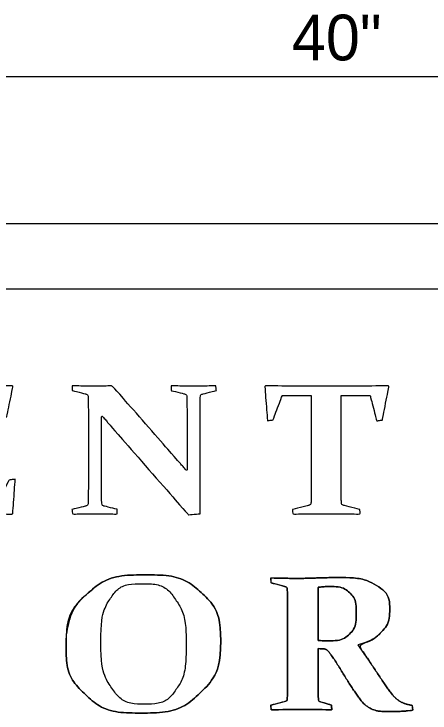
# Model space of a CAD drawing. Extents: x 60714 to 61343, y 7599 to 7998.
# Drawn here: x 60981.17 to 61006.63, y 7950.27 to 7993.09 of the extents above; entities that cross this region are included whole.
import ezdxf

# ---------------------------------------------------------------- set-up
doc = ezdxf.new("R2010")
doc.units = 0
for name, color, linetype in [('2', 7, 'Continuous'), ('Default', 7, 'Continuous'), ('SignPanel', 7, 'Continuous')]:
    doc.layers.add(name, color=color, linetype=linetype)

# ---------------------------------------------------------------- blocks, each defined once
blk = doc.blocks.new('block 5')
at = {"layer": 'Default'}
for points in [[(437.3, -454.8), (437.3, -454.8), (448.38, -454.8), (448.38, -454.8), (455.48, -454.8), (462.84, -454.75), (470.47, -454.63), (470.47, -454.63), (470.77, -454.98), (470.77, -454.98), (470.77, -454.98), (468.06, -469.57), (468.06, -469.57), (468.06, -469.57), (465.69, -469.92), (465.69, -469.92), (465.69, -469.92), (462.89, -459.27), (462.89, -459.27), (462.89, -459.27), (445.93, -459.27), (445.93, -459.27), (445.93, -459.27), (445.93, -482.54), (445.93, -482.54), (445.93, -482.54), (448.3, -482.54), (448.3, -482.54), (450.84, -482.54), (453.57, -482.51), (456.49, -482.45), (457.25, -482.42), (457.75, -482.03), (457.98, -481.27), (457.98, -481.27), (459.56, -475.27), (459.56, -475.27), (459.56, -475.27), (462.45, -475.13), (462.45, -475.13), (462.36, -479.37), (462.32, -482.54), (462.32, -484.64), (462.32, -486.69), (462.36, -489.81), (462.45, -494.02), (462.45, -494.02), (459.56, -494.24), (459.56, -494.24), (459.56, -494.24), (457.94, -488.06), (457.94, -488.06), (457.7, -487.27), (457.25, -486.86), (456.58, -486.83), (453.6, -486.78), (450.82, -486.75), (448.25, -486.75), (448.25, -486.75), (445.93, -486.75), (445.93, -486.75), (445.93, -486.75), (445.93, -501.78), (445.93, -501.78), (445.93, -504.99), (445.96, -508.17), (446.02, -511.33), (446.02, -511.33), (463.54, -511.33), (463.54, -511.33), (463.54, -511.33), (469.06, -499.8), (469.06, -499.8), (469.06, -499.8), (471.74, -499.41), (471.74, -499.41), (471.74, -499.41), (470.69, -515.8), (470.69, -515.8), (470.69, -515.8), (470.38, -516.1), (470.38, -516.1), (463.11, -516.02), (456.02, -515.97), (449.13, -515.97), (449.13, -515.97), (437.52, -515.97), (437.52, -515.97), (433.75, -515.97), (429.86, -516.02), (425.86, -516.1), (425.86, -516.1), (425.64, -513.91), (425.64, -513.91), (425.64, -513.91), (431.51, -512.29), (431.51, -512.29), (432.24, -512.09), (432.64, -511.64), (432.7, -510.93), (432.73, -509.77), (432.75, -508.46), (432.76, -507.01), (432.78, -505.57), (432.78, -503.97), (432.78, -502.21), (432.78, -502.21), (432.78, -467.29), (432.78, -467.29), (432.78, -465.83), (432.78, -464.5), (432.76, -463.3), (432.75, -462.11), (432.73, -461.01), (432.7, -460.02), (432.67, -459.26), (432.32, -458.78), (431.64, -458.57), (431.64, -458.57), (425.77, -456.86), (425.77, -456.86), (425.77, -456.86), (425.64, -454.63), (425.64, -454.63), (429.73, -454.75), (433.62, -454.8), (437.3, -454.8)], [(437.3, -454.8), (437.3, -454.8), (448.38, -454.8), (448.38, -454.8), (455.48, -454.8), (462.84, -454.75), (470.47, -454.63), (470.47, -454.63), (470.77, -454.98), (470.77, -454.98), (470.77, -454.98), (468.06, -469.57), (468.06, -469.57), (468.06, -469.57), (465.69, -469.92), (465.69, -469.92), (465.69, -469.92), (462.89, -459.27), (462.89, -459.27), (462.89, -459.27), (445.93, -459.27), (445.93, -459.27), (445.93, -459.27), (445.93, -482.54), (445.93, -482.54), (445.93, -482.54), (448.3, -482.54), (448.3, -482.54), (450.84, -482.54), (453.57, -482.51), (456.49, -482.45), (457.25, -482.42), (457.75, -482.03), (457.98, -481.27), (457.98, -481.27), (459.56, -475.27), (459.56, -475.27), (459.56, -475.27), (462.45, -475.13), (462.45, -475.13), (462.36, -479.37), (462.32, -482.54), (462.32, -484.64), (462.32, -486.69), (462.36, -489.81), (462.45, -494.02), (462.45, -494.02), (459.56, -494.24), (459.56, -494.24), (459.56, -494.24), (457.94, -488.06), (457.94, -488.06), (457.7, -487.27), (457.25, -486.86), (456.58, -486.83), (453.6, -486.78), (450.82, -486.75), (448.25, -486.75), (448.25, -486.75), (445.93, -486.75), (445.93, -486.75), (445.93, -486.75), (445.93, -501.78), (445.93, -501.78), (445.93, -504.99), (445.96, -508.17), (446.02, -511.33), (446.02, -511.33), (463.54, -511.33), (463.54, -511.33), (463.54, -511.33), (469.06, -499.8), (469.06, -499.8), (469.06, -499.8), (471.74, -499.41), (471.74, -499.41), (471.74, -499.41), (470.69, -515.8), (470.69, -515.8), (470.69, -515.8), (470.38, -516.1), (470.38, -516.1), (463.11, -516.02), (456.02, -515.97), (449.13, -515.97), (449.13, -515.97), (437.52, -515.97), (437.52, -515.97), (433.75, -515.97), (429.86, -516.02), (425.86, -516.1), (425.86, -516.1), (425.64, -513.91), (425.64, -513.91), (425.64, -513.91), (431.51, -512.29), (431.51, -512.29), (432.24, -512.09), (432.64, -511.64), (432.7, -510.93), (432.73, -509.77), (432.75, -508.46), (432.76, -507.01), (432.78, -505.57), (432.78, -503.97), (432.78, -502.21), (432.78, -502.21), (432.78, -467.29), (432.78, -467.29), (432.78, -465.83), (432.78, -464.5), (432.76, -463.3), (432.75, -462.11), (432.73, -461.01), (432.7, -460.02), (432.67, -459.26), (432.32, -458.78), (431.64, -458.57), (431.64, -458.57), (425.77, -456.86), (425.77, -456.86), (425.77, -456.86), (425.64, -454.63), (425.64, -454.63), (429.73, -454.75), (433.62, -454.8), (437.3, -454.8)], [(509.49, -510.76), (509.52, -511.61), (509.89, -512.12), (510.59, -512.29), (510.59, -512.29), (516.2, -513.83), (516.2, -513.83), (516.2, -513.83), (516.33, -516.1), (516.33, -516.1), (512.38, -516.02), (509.14, -515.97), (506.6, -515.97), (504.09, -515.97), (500.8, -516.02), (496.74, -516.1), (496.74, -516.1), (496.52, -513.91), (496.52, -513.91), (496.52, -513.91), (502.39, -512.29), (502.39, -512.29), (503.15, -512.06), (503.55, -511.61), (503.58, -510.93), (503.63, -508.57), (503.66, -505.66), (503.66, -502.21), (503.66, -502.21), (503.66, -467.29), (503.66, -467.29), (503.66, -464.37), (503.63, -461.95), (503.58, -460.02), (503.55, -459.26), (503.2, -458.78), (502.52, -458.57), (502.52, -458.57), (496.65, -456.86), (496.65, -456.86), (496.65, -456.86), (496.52, -454.63), (496.52, -454.63), (500.61, -454.75), (503.75, -454.8), (505.94, -454.8), (508.8, -454.8), (511.52, -454.75), (514.09, -454.63), (514.09, -454.63), (543.23, -491.13), (543.23, -491.13), (544.4, -492.59), (545.6, -494.14), (546.82, -495.77), (546.77, -493.76), (546.74, -491.81), (546.74, -489.95), (546.74, -489.95), (546.74, -467.12), (546.74, -467.12), (546.74, -464.28), (546.71, -461.84), (546.65, -459.8), (546.62, -459.13), (546.24, -458.69), (545.51, -458.48), (545.51, -458.48), (539.9, -456.95), (539.9, -456.95), (539.9, -456.95), (539.77, -454.63), (539.77, -454.63), (543.8, -454.75), (547.07, -454.8), (549.58, -454.8), (552.16, -454.8), (555.41, -454.75), (559.36, -454.63), (559.36, -454.63), (559.57, -456.86), (559.57, -456.86), (559.57, -456.86), (553.62, -458.57), (553.62, -458.57), (552.94, -458.78), (552.59, -459.26), (552.56, -460.02), (552.48, -461.95), (552.43, -464.37), (552.43, -467.29), (552.43, -467.29), (552.43, -515.97), (552.43, -515.97), (552.43, -515.97), (547.39, -516.45), (547.39, -516.45), (547.39, -516.45), (512.87, -473.21), (512.87, -473.21), (511.84, -471.89), (510.66, -470.33), (509.32, -468.52), (509.37, -470.68), (509.4, -472.67), (509.4, -474.48), (509.4, -474.48), (509.4, -502.21), (509.4, -502.21), (509.4, -505.66), (509.43, -508.51), (509.49, -510.76)], [(509.49, -510.76), (509.52, -511.61), (509.89, -512.12), (510.59, -512.29), (510.59, -512.29), (516.2, -513.83), (516.2, -513.83), (516.2, -513.83), (516.33, -516.1), (516.33, -516.1), (512.38, -516.02), (509.14, -515.97), (506.6, -515.97), (504.09, -515.97), (500.8, -516.02), (496.74, -516.1), (496.74, -516.1), (496.52, -513.91), (496.52, -513.91), (496.52, -513.91), (502.39, -512.29), (502.39, -512.29), (503.15, -512.06), (503.55, -511.61), (503.58, -510.93), (503.63, -508.57), (503.66, -505.66), (503.66, -502.21), (503.66, -502.21), (503.66, -467.29), (503.66, -467.29), (503.66, -464.37), (503.63, -461.95), (503.58, -460.02), (503.55, -459.26), (503.2, -458.78), (502.52, -458.57), (502.52, -458.57), (496.65, -456.86), (496.65, -456.86), (496.65, -456.86), (496.52, -454.63), (496.52, -454.63), (500.61, -454.75), (503.75, -454.8), (505.94, -454.8), (508.8, -454.8), (511.52, -454.75), (514.09, -454.63), (514.09, -454.63), (543.23, -491.13), (543.23, -491.13), (544.4, -492.59), (545.6, -494.14), (546.82, -495.77), (546.77, -493.76), (546.74, -491.81), (546.74, -489.95), (546.74, -489.95), (546.74, -467.12), (546.74, -467.12), (546.74, -464.28), (546.71, -461.84), (546.65, -459.8), (546.62, -459.13), (546.24, -458.69), (545.51, -458.48), (545.51, -458.48), (539.9, -456.95), (539.9, -456.95), (539.9, -456.95), (539.77, -454.63), (539.77, -454.63), (543.8, -454.75), (547.07, -454.8), (549.58, -454.8), (552.16, -454.8), (555.41, -454.75), (559.36, -454.63), (559.36, -454.63), (559.57, -456.86), (559.57, -456.86), (559.57, -456.86), (553.62, -458.57), (553.62, -458.57), (552.94, -458.78), (552.59, -459.26), (552.56, -460.02), (552.48, -461.95), (552.43, -464.37), (552.43, -467.29), (552.43, -467.29), (552.43, -515.97), (552.43, -515.97), (552.43, -515.97), (547.39, -516.45), (547.39, -516.45), (547.39, -516.45), (512.87, -473.21), (512.87, -473.21), (511.84, -471.89), (510.66, -470.33), (509.32, -468.52), (509.37, -470.68), (509.4, -472.67), (509.4, -474.48), (509.4, -474.48), (509.4, -502.21), (509.4, -502.21), (509.4, -505.66), (509.43, -508.51), (509.49, -510.76)], [(607.67, -515.97), (602.53, -515.97), (597.62, -516.02), (592.94, -516.1), (592.94, -516.1), (592.73, -513.91), (592.73, -513.91), (592.73, -513.91), (599.74, -511.99), (599.74, -511.99), (600.47, -511.75), (600.85, -511.28), (600.88, -510.58), (600.93, -508.39), (600.96, -505.57), (600.96, -502.13), (600.96, -502.13), (600.96, -459.32), (600.96, -459.32), (600.96, -459.32), (588.34, -459.32), (588.34, -459.32), (588.34, -459.32), (584.31, -470.97), (584.31, -470.97), (584.31, -470.97), (581.86, -471.37), (581.86, -471.37), (581.86, -471.37), (580.72, -454.98), (580.72, -454.98), (580.72, -454.98), (581.03, -454.63), (581.03, -454.63), (588.21, -454.75), (595.09, -454.8), (601.66, -454.8), (601.66, -454.8), (613.89, -454.8), (613.89, -454.8), (620.46, -454.8), (627.39, -454.75), (634.66, -454.63), (634.66, -454.63), (634.92, -454.98), (634.92, -454.98), (634.92, -454.98), (632.03, -471.02), (632.03, -471.02), (632.03, -471.02), (629.58, -471.41), (629.58, -471.41), (629.58, -471.41), (626.73, -459.32), (626.73, -459.32), (626.73, -459.32), (614.06, -459.32), (614.06, -459.32), (614.06, -459.32), (614.06, -502.13), (614.06, -502.13), (614.06, -505.57), (614.09, -508.39), (614.15, -510.58), (614.18, -511.28), (614.58, -511.75), (615.34, -511.99), (615.34, -511.99), (622.21, -513.91), (622.21, -513.91), (622.21, -513.91), (622.35, -516.1), (622.35, -516.1), (617.5, -516.02), (612.6, -515.97), (607.67, -515.97)], [(607.67, -515.97), (602.53, -515.97), (597.62, -516.02), (592.94, -516.1), (592.94, -516.1), (592.73, -513.91), (592.73, -513.91), (592.73, -513.91), (599.74, -511.99), (599.74, -511.99), (600.47, -511.75), (600.85, -511.28), (600.88, -510.58), (600.93, -508.39), (600.96, -505.57), (600.96, -502.13), (600.96, -502.13), (600.96, -459.32), (600.96, -459.32), (600.96, -459.32), (588.34, -459.32), (588.34, -459.32), (588.34, -459.32), (584.31, -470.97), (584.31, -470.97), (584.31, -470.97), (581.86, -471.37), (581.86, -471.37), (581.86, -471.37), (580.72, -454.98), (580.72, -454.98), (580.72, -454.98), (581.03, -454.63), (581.03, -454.63), (588.21, -454.75), (595.09, -454.8), (601.66, -454.8), (601.66, -454.8), (613.89, -454.8), (613.89, -454.8), (620.46, -454.8), (627.39, -454.75), (634.66, -454.63), (634.66, -454.63), (634.92, -454.98), (634.92, -454.98), (634.92, -454.98), (632.03, -471.02), (632.03, -471.02), (632.03, -471.02), (629.58, -471.41), (629.58, -471.41), (629.58, -471.41), (626.73, -459.32), (626.73, -459.32), (626.73, -459.32), (614.06, -459.32), (614.06, -459.32), (614.06, -459.32), (614.06, -502.13), (614.06, -502.13), (614.06, -505.57), (614.09, -508.39), (614.15, -510.58), (614.18, -511.28), (614.58, -511.75), (615.34, -511.99), (615.34, -511.99), (622.21, -513.91), (622.21, -513.91), (622.21, -513.91), (622.35, -516.1), (622.35, -516.1), (617.5, -516.02), (612.6, -515.97), (607.67, -515.97)]]:
    blk.add_open_spline(points, degree=3, dxfattribs=at)
blk = doc.blocks.new('block 8')
at = {"layer": 'Default'}
for p, q in [((604, -551.2), (604, -576.68)), ((590.62, -595.65), (590.62, -559.75)), ((645.12, -607.8), (645.3, -610.1))]:
    blk.add_line(p, q, dxfattribs=at)
for points in [[(589.45, -550.79), (583.42, -549.04), (583.29, -546.74)], [(605.89, -580.65), (604, -580.6), (604, -595.65)], [(583.51, -609.92), (583.29, -607.67), (589.32, -606)], [(605.13, -606.14), (609.81, -607.67), (609.95, -609.92)]]:
    blk.add_lwpolyline(points, dxfattribs=at)
for points in [[(561.49, -576.91), (561.49, -587.3), (558.43, -595.65), (552.31, -601.97), (546.18, -608.3), (537.65, -611.45), (526.73, -611.45), (516.28, -611.45), (508.2, -608.53), (502.5, -602.69), (496.79, -596.86), (493.94, -588.95), (493.94, -578.98), (493.94, -568.6), (497.02, -560.38), (503.17, -554.33), (509.33, -548.28), (517.84, -545.25), (528.71, -545.25), (539.16, -545.25), (547.23, -548.08), (552.93, -553.74), (558.64, -559.4), (561.49, -567.12), (561.49, -576.91)], [(494.63, -570.94), (495.86, -564.26), (498.7, -558.72), (503.17, -554.33), (509.33, -548.28), (517.84, -545.25), (528.71, -545.25), (539.16, -545.25), (547.23, -548.08), (552.93, -553.74), (558.64, -559.4), (561.49, -567.12), (561.49, -576.91)], [(604, -595.65), (604, -597.45), (604.01, -599.06), (604.02, -600.49), (604.04, -601.91), (604.06, -603.21), (604.09, -604.38), (604.12, -605.35), (604.46, -605.93), (605.13, -606.14), (605.13, -606.14), (609.81, -607.67), (609.81, -607.67), (609.81, -607.67), (609.95, -609.92), (609.95, -609.92), (606.61, -609.83), (602.48, -609.79), (597.56, -609.79), (592.31, -609.79), (587.62, -609.83), (583.51, -609.92), (583.51, -609.92), (583.29, -607.67), (583.29, -607.67), (583.29, -607.67), (589.32, -606), (589.32, -606), (590.07, -605.79), (590.47, -605.33), (590.53, -604.61), (590.56, -603.41), (590.59, -602.06), (590.6, -600.58), (590.62, -599.09), (590.62, -597.45), (590.62, -595.65), (590.62, -595.65), (590.62, -559.75), (590.62, -559.75), (590.62, -558.25), (590.62, -556.89), (590.6, -555.65), (590.59, -554.42), (590.56, -553.3), (590.53, -552.28), (590.51, -551.5), (590.14, -551), (589.45, -550.79), (589.45, -550.79), (583.42, -549.04), (583.42, -549.04), (583.42, -549.04), (583.29, -546.74), (583.29, -546.74), (587.49, -546.86), (591.8, -546.92), (596.21, -546.92), (597.14, -546.92), (598.3, -546.9), (599.68, -546.85), (601.06, -546.81), (602.74, -546.75), (604.72, -546.69), (606.52, -546.63), (608.03, -546.59), (609.24, -546.56), (610.46, -546.53), (611.42, -546.51), (612.11, -546.51), (619.82, -546.51), (625.61, -547.8), (629.47, -550.38), (633.32, -552.97), (635.25, -556.74), (635.25, -561.69), (635.25, -566.16), (634.07, -569.77), (631.72, -572.52), (629.36, -575.27), (625.9, -577.38), (621.34, -578.85), (623.86, -582.57), (625.8, -585.59), (627.17, -587.9), (628.53, -590.21), (629.91, -592.49), (631.29, -594.72), (632.67, -596.96), (633.92, -598.93), (635.05, -600.64), (636.18, -602.36), (637.23, -603.71), (638.23, -604.7), (638.77, -605.15), (639.28, -605.54), (639.78, -605.87), (640.28, -606.2), (640.79, -606.49), (641.33, -606.72), (641.87, -606.96), (642.45, -607.17), (643.07, -607.33), (643.68, -607.5), (644.37, -607.65), (645.12, -607.8), (645.12, -607.8), (645.3, -610.1), (645.3, -610.1), (642.36, -610.52), (638.99, -610.73), (635.21, -610.73), (632.2, -610.73), (630.11, -610.54), (628.9, -610.15), (627.7, -609.76), (626.64, -609.2), (625.71, -608.48), (624.33, -607.4), (623.06, -605.99), (621.9, -604.25), (620.74, -602.51), (619.52, -600.54), (618.23, -598.35), (616.94, -596.16), (615.61, -593.83), (614.24, -591.37), (612.88, -588.9), (611.45, -586.47), (609.95, -584.07), (609.49, -583.38), (609.13, -582.81), (608.84, -582.36), (608.55, -581.91), (608.27, -581.57), (607.98, -581.35), (607.7, -581.12), (607.4, -580.96), (607.08, -580.85), (606.77, -580.75), (606.37, -580.68), (605.89, -580.65), (605.89, -580.65), (604, -580.6), (604, -580.6), (604, -580.6), (604, -595.65), (604, -595.65)], [(583.29, -546.74), (587.49, -546.86), (591.8, -546.92), (596.21, -546.92), (597.14, -546.92), (598.3, -546.9), (599.68, -546.85), (601.06, -546.81), (602.74, -546.75), (604.72, -546.69), (606.52, -546.63), (608.03, -546.59), (609.24, -546.56), (610.46, -546.53), (611.42, -546.51), (612.11, -546.51), (619.82, -546.51), (625.61, -547.8), (629.47, -550.38), (633.32, -552.97), (635.25, -556.74), (635.25, -561.69), (635.25, -566.16), (634.07, -569.77), (631.72, -572.52), (629.36, -575.27), (625.9, -577.38), (621.34, -578.85)], [(509.07, -577.5), (509.07, -587.1), (510.69, -594.45), (513.94, -599.54), (517.18, -604.63), (521.94, -607.18), (528.21, -607.18), (534.4, -607.18), (538.97, -604.86), (541.92, -600.24), (544.88, -595.62), (546.36, -588.35), (546.36, -578.44), (546.36, -569.14), (544.8, -561.98), (541.68, -556.98), (538.55, -551.98), (533.72, -549.48), (527.17, -549.48), (520.84, -549.48), (516.24, -551.8), (513.37, -556.44), (510.5, -561.08), (509.07, -568.1), (509.07, -577.5)], [(509.07, -577.5), (509.07, -587.1), (510.69, -594.45), (513.94, -599.54), (517.18, -604.63), (521.94, -607.18), (528.21, -607.18), (534.4, -607.18), (538.97, -604.86), (541.92, -600.24), (544.88, -595.62), (546.36, -588.35), (546.36, -578.44), (546.36, -569.14), (544.8, -561.98), (541.68, -556.98), (538.55, -551.98), (533.72, -549.48), (527.17, -549.48), (520.84, -549.48), (516.24, -551.8), (513.37, -556.44), (510.5, -561.08), (509.07, -568.1), (509.07, -577.5)], [(590.62, -559.75), (590.62, -558.25), (590.62, -556.89), (590.6, -555.65), (590.59, -554.42), (590.56, -553.3), (590.53, -552.28), (590.51, -551.5), (590.14, -551), (589.45, -550.79)], [(604, -576.68), (605.59, -576.78), (607.03, -576.82), (608.32, -576.82), (612.58, -576.82), (615.71, -575.75), (617.69, -573.6), (619.67, -571.46), (620.66, -568.1), (620.66, -563.53), (620.66, -559.12), (619.71, -555.9), (617.8, -553.88), (615.9, -551.85), (612.93, -550.84), (608.91, -550.84), (608.22, -550.84), (607.47, -550.87), (606.68, -550.92), (605.89, -550.99), (604.99, -551.08), (604, -551.2), (604, -551.2), (604, -576.68), (604, -576.68)], [(604, -576.68), (605.59, -576.78), (607.03, -576.82), (608.32, -576.82), (612.58, -576.82), (615.71, -575.75), (617.69, -573.6), (619.67, -571.46), (620.66, -568.1), (620.66, -563.53), (620.66, -559.12), (619.71, -555.9), (617.8, -553.88), (615.9, -551.85), (612.93, -550.84), (608.91, -550.84), (608.22, -550.84), (607.47, -550.87), (606.68, -550.92), (605.89, -550.99), (604.99, -551.08), (604, -551.2)], [(561.49, -576.91), (561.49, -587.3), (558.43, -595.65), (552.31, -601.97), (546.18, -608.3), (537.65, -611.45), (526.73, -611.45), (516.28, -611.45), (508.2, -608.53), (502.5, -602.69), (496.79, -596.86), (493.94, -588.95), (493.94, -578.98), (493.94, -576.14), (494.17, -573.46), (494.63, -570.94)], [(621.34, -578.85), (623.86, -582.57), (625.8, -585.59), (627.17, -587.9), (628.53, -590.21), (629.91, -592.49), (631.29, -594.72), (632.67, -596.96), (633.92, -598.93), (635.05, -600.64), (636.18, -602.36), (637.23, -603.71), (638.23, -604.7), (638.77, -605.15), (639.28, -605.54), (639.78, -605.87), (640.28, -606.2), (640.79, -606.49), (641.33, -606.72), (641.87, -606.96), (642.45, -607.17), (643.07, -607.33), (643.68, -607.5), (644.37, -607.65), (645.12, -607.8)], [(645.3, -610.1), (642.36, -610.52), (638.99, -610.73), (635.21, -610.73), (632.2, -610.73), (630.11, -610.54), (628.9, -610.15), (627.7, -609.76), (626.64, -609.2), (625.71, -608.48), (624.33, -607.4), (623.06, -605.99), (621.9, -604.25), (620.74, -602.51), (619.52, -600.54), (618.23, -598.35), (616.94, -596.16), (615.61, -593.83), (614.24, -591.37), (612.88, -588.9), (611.45, -586.47), (609.95, -584.07), (609.49, -583.38), (609.13, -582.81), (608.84, -582.36), (608.55, -581.91), (608.27, -581.57), (607.98, -581.35), (607.7, -581.12), (607.4, -580.96), (607.08, -580.85), (606.77, -580.75), (606.37, -580.68), (605.89, -580.65)], [(589.32, -606), (590.07, -605.79), (590.47, -605.33), (590.53, -604.61), (590.56, -603.41), (590.59, -602.06), (590.6, -600.58), (590.62, -599.09), (590.62, -597.45), (590.62, -595.65)], [(604, -595.65), (604, -597.45), (604.01, -599.06), (604.02, -600.49), (604.04, -601.91), (604.06, -603.21), (604.09, -604.38), (604.12, -605.35), (604.46, -605.93), (605.13, -606.14)], [(609.95, -609.92), (606.61, -609.83), (602.48, -609.79), (597.56, -609.79), (592.31, -609.79), (587.62, -609.83), (583.51, -609.92)]]:
    blk.add_open_spline(points, degree=3, dxfattribs=at)

msp = doc.modelspace()

# ---------------------------------------------------------------- linework, layer by layer
at = {"layer": '2'}
msp.add_line((60960.568, 7989.258), (61040.577, 7989.258), dxfattribs=at)
at = {"layer": 'SignPanel'}
msp.add_lwpolyline([(60960.568, 7980.258), (61040.577, 7980.258), (61040.577, 7976.231), (60960.568, 7976.231), (60960.568, 7980.258)], dxfattribs=at)

# ---------------------------------------------------------------- block references
at = {"layer": 'SignPanel', "xscale": 0.14019599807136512, "yscale": 0.1278006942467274, "rotation": -6.923017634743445e-08}
for name in ['block 5', 'block 8']:
    msp.add_blockref(name, (60915.109, 8028.418), dxfattribs=at)

# ---------------------------------------------------------------- texts
at = {"layer": '2'}
msp.add_text('40"', height=2.8, dxfattribs=at).set_placement((60998.177, 7990.246))

doc.saveas('drawing.dxf')
